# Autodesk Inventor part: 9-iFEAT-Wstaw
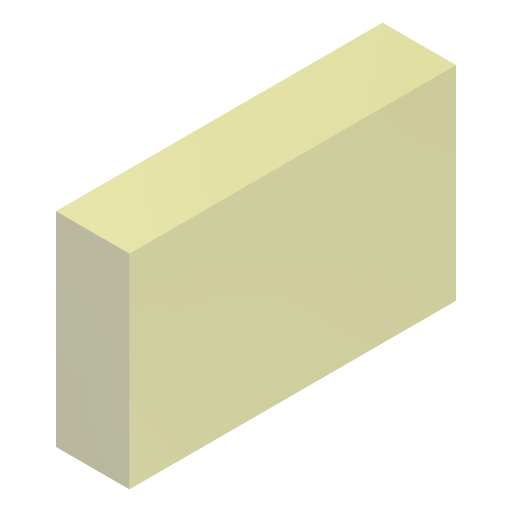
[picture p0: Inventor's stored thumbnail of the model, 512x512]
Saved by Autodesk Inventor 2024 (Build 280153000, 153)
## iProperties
Company: ATC
Shininess: 64.0
Length Units: 11269
Angle Units: 11279
Time Units: 11290
Mass Units: 11283
Length Display Precision: 3
Angle Display Precision: 2
Compacted: True
Part Number: 9-iFEAT-Wstaw
Document SubType Name: Modeling
Created: 2023-03
Material: Kurs-AJ
Designer: Andrzej Jaskulski
Manufacturer: Standard
Standards Organization: Custom
Density: 1 g/cm^3
Appearance: Przezroczysty - żółty
Checked By: A.J.
Engr Approved By: Andrzej Jaskulski
Mfg Approved By: Andrzej Jaskulski
Authority: A.J.
Density: 0.0
Volumn: 0.0
Area: 0.0
PropertySet Name: Model Information
Control State: 0
Master: False
Checked Out: False
Title: A.J.: Kurs R2024-MEP
Author: Andrzej Jaskulski
Revision Number: 1/24
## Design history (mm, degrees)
sketch "Szkic1"
  geometry: L1 (0, 0)-(18, 0); L2 (18, 0)-(18, 80); L3 (18, 80)-(0, 80); L4 (0, 80)-(0, 0)
  constraints: 8 end point, 2 parallel, 1 horizontal, 1 perpendicular, 1 other
  dimensions: "GRUBplyty" = 18 distance of L1.start L1.end; "d2" = 80 distance of L3.end L1.start
extrude "Wyciągnięcie proste1" new body sketch "Szkic1" distance "d0" = 50; taper "d1" = 0 deg
node "Bryła1"
node "Korpusy bryłowe"
node "Korpusy powierzchniowe"
